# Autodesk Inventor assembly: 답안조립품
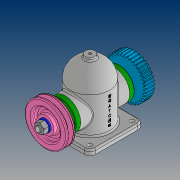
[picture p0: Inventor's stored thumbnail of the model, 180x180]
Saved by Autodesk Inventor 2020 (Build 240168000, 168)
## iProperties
Created: 2021-08
Part Number: 답안조립품
Document SubType Name: Assembly
Designer: PC312-
Author: PC312-
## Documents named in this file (13)
- C:\Users\PC312-\Desktop\710809V1001\답안조립품.iam
- C:\Users\PC312-\Desktop\710809V1001\본체.ipt
- C:\Users\PC312-\Desktop\710809V1001\베어링 6203.ipt
- C:\Users\PC312-\Desktop\710809V1001\축.ipt
- C:\Users\PC312-\Desktop\710809V1001\커버.ipt
- C:\Users\PC312-\Desktop\710809V1001\오일 실 26 38 8.ipt
- C:\Users\PC312-\Desktop\710809V1001\부시.ipt
- C:\Users\PC312-\Desktop\710809V1001\키 5x5x12.ipt
- C:\Users\PC312-\Desktop\710809V1001\V-벨트풀리.ipt
- V-벨트풀리.ipt
- C:\Users\PC312-\Desktop\710809V1001\스퍼기어.ipt
- C:\Users\PC312-\Desktop\710809V1001\너트 M12x1.25.ipt
- C:\Users\PC312-\Desktop\710809V1001\와셔 12x24.ipt
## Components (1 placed, 1 different names)
1. V-벨트풀리:1
